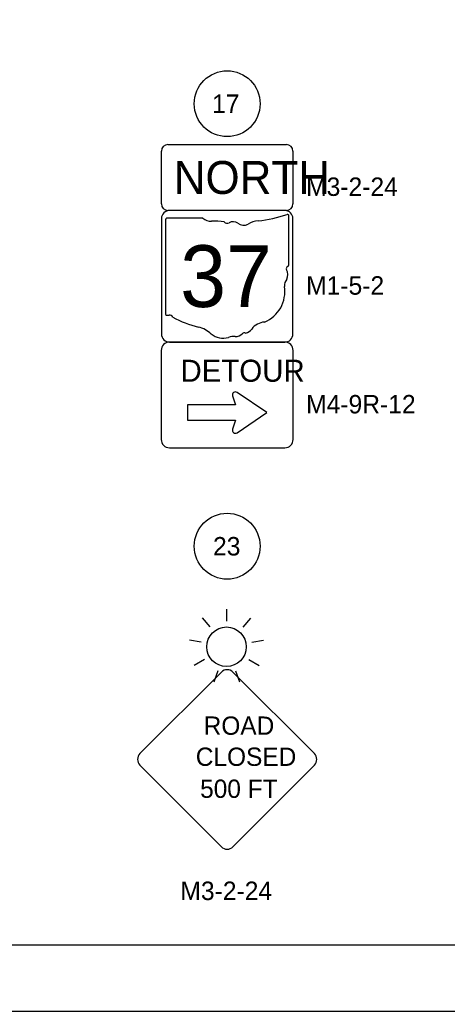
# Model space of a CAD drawing. Extents: x 0 to 680, y 0 to 440.
# Drawn here: x 514.2 to 579.2, y 0 to 150.5 of the extents above; entities that cross this region are included whole.
import ezdxf

# ---------------------------------------------------------------- set-up
doc = ezdxf.new("R2010")
doc.units = 0
for name, color, linetype in [('AP_X_Lights', 7, 'Continuous'), ('SH_Border', 7, 'Continuous'), ('SH_Cut_Line', 7, 'Continuous'), ('SN_P_Signs', 7, 'Continuous'), ('SN_P_Text', 7, 'Continuous')]:
    doc.layers.add(name, color=color, linetype=linetype)

msp = doc.modelspace()

# ---------------------------------------------------------------- linework, layer by layer
at = {"layer": 'AP_X_Lights'}
for p, q in [((545.7, 59.24), (545.7, 61.04)), ((543.18, 58.35), (542.02, 59.73)), ((548.19, 58.31), (549.34, 59.69)), ((541.82, 56.03), (540.05, 56.34)), ((549.5, 56.02), (551.27, 56.33)), ((542.29, 53.38), (540.73, 52.48)), ((549.05, 53.41), (550.61, 52.51)), ((544.36, 51.66), (543.74, 49.97)), ((547.03, 51.69), (547.65, 50))]:
    msp.add_line(p, q, dxfattribs=at)
msp.add_circle((545.66, 55.34), 3, dxfattribs=at)
at = {"layer": 'SH_Border'}
msp.add_lwpolyline([(30, 430), (670, 430), (670, 10), (30, 10)], close=True, dxfattribs=at)
at = {"layer": 'SH_Cut_Line'}
msp.add_lwpolyline([(0, 0), (680, 0), (680, 440), (0, 440)], close=True, dxfattribs=at)
at = {"layer": 'SN_P_Signs'}
for p, q in [((536.76, 131.6), (554.76, 131.6)), ((535.76, 122.6), (535.76, 130.6)), ((555.76, 130.6), (555.76, 122.6)), ((554.76, 121.6), (536.76, 121.6)), ((555.12, 113.31), (555.12, 120.76)), ((536.37, 120.16), (536.37, 105.93)), ((542.05, 120.4), (536.56, 120.4)), ((555.12, 113.31), (555.12, 113.31)), ((546.58, 93.44), (547.01, 92.07)), ((551.78, 90.9), (547.27, 93.96)), ((547.01, 92.07), (539.74, 92.07)), ((539.74, 92.07), (539.74, 89.73)), ((547.27, 87.84), (551.78, 90.9)), ((539.74, 89.73), (547.01, 89.73)), ((547.01, 89.73), (546.58, 88.36))]:
    msp.add_line(p, q, dxfattribs=at)
for points in [[(554.51, 121.6), (537.01, 121.6)], [(535.76, 120.35), (535.76, 102.85)], [(555.76, 102.85), (555.76, 120.35)], [(537.01, 101.6), (554.51, 101.6)], [(554.51, 101.6), (537.01, 101.6)], [(535.73, 100.32), (535.73, 86.83)], [(555.79, 86.83), (555.79, 100.32)], [(537.01, 85.54), (554.51, 85.54)], [(532.5, 39.11), (544.88, 51.48)], [(546.64, 51.48), (559.02, 39.11)], [(544.88, 24.97), (532.5, 37.34)], [(559.02, 37.34), (546.64, 24.97)]]:
    msp.add_lwpolyline(points, dxfattribs=at)
for centre in [(545.76, 137.8), (545.76, 70.6)]:
    msp.add_circle(centre, 5, dxfattribs=at)
for centre, radius, start, end in [((536.76, 130.6), 1, 90, 180), ((554.76, 130.6), 1, 0, 90), ((536.76, 122.6), 1, 180, 270), ((554.76, 122.6), 1, 270, 0), ((537.01, 120.35), 1.25, 90, 180), ((548.44, 139.8), 19.88, 275.8445, 288.9065), ((554.51, 120.35), 1.25, 0, 90), ((554.91, 120.79), 0.209, 351.8621, 97.738), ((536.59, 120.19), 0.217, 98.1301, 188.1301), ((543.35, 122.06), 2.11, 231.6195, 271.1119), ((544.05, 112.41), 7.56, 80.4867, 94.9883), ((545.77, 120.26), 0.608, 219.7921, 297.1024), ((546.66, 118.62), 1.26, 54.4667, 119.1411), ((548.29, 120.87), 1.52, 233.8562, 294.8282), ((550.98, 116.06), 4, 97.3462, 120.7689), ((555.07, 112.77), 0.323, 107.944, 210.337), ((554.9, 113.28), 0.223, 289.6038, 7.7341), ((553.02, 111.82), 1.94, 340.033, 23.6496), ((549.56, 109.25), 4.97, 292.3089, 8.9858), ((555.87, 110.2), 1.41, 136.8065, 186.9296), ((536.59, 105.9), 0.219, 171.9584, 258.3066), ((536.62, 107.35), 1.67, 267.339, 280.6039), ((536.96, 105.11), 0.603, 29.7484, 93.2717), ((544.58, 117.89), 14.36, 240.4129, 257.1985), ((540.3, 99.53), 4.49, 47.1842, 75.836), ((551.65, 101.93), 2.72, 94.4031, 142.5768), ((537.01, 102.85), 1.25, 180, 270), ((545.15, 105.04), 2.85, 230.7004, 286.2918), ((546.8, 100.12), 2.34, 85.6951, 111.2099), ((547.01, 103.97), 1.52, 268.777, 315.5493), ((548.38, 102.59), 0.428, 65.7517, 132.6484), ((548.2, 104.55), 1.61, 282.8732, 323.2771), ((554.51, 102.85), 1.25, 270, 0), ((537.01, 100.32), 1.28, 90, 180), ((554.51, 100.32), 1.28, 0, 90), ((547.01, 93.58), 0.459, 55.8031, 197.8008), ((547.01, 88.22), 0.459, 162.1992, 304.1969), ((537.01, 86.83), 1.28, 180, 270), ((554.51, 86.83), 1.28, 270, 0), ((545.76, 50.6), 1.25, 45, 135), ((533.39, 38.23), 1.25, 135, 225), ((558.13, 38.23), 1.25, 315, 45), ((545.76, 25.85), 1.25, 225, 315)]:
    msp.add_arc(centre, radius, start, end, dxfattribs=at)

# ---------------------------------------------------------------- texts
for s, height, p in [('17', 2.8, (543.46, 136.4)), ('NORTH', 5, (537.63, 124.1)), ('37', 9.375, (538.62, 106.93)), ('DETOUR', 3.345, (538.66, 95.58)), ('23', 2.8, (543.61, 69.2)), ('ROAD', 2.778, (542.19, 41.97)), ('CLOSED', 2.778, (540.99, 37.25)), ('500 FT', 2.778, (541.65, 32.39))]:
    msp.add_text(s, height=height, dxfattribs=at).set_placement(p)
at = {"layer": 'SN_P_Text'}
for s, p in [('M3-2-24', (557.76, 123.8)), ('M1-5-2', (557.76, 108.8)), ('M4-9R-12', (557.76, 90.77)), ('M3-2-24', (538.65, 16.88))]:
    msp.add_text(s, height=2.8, dxfattribs=at).set_placement(p)

doc.saveas('drawing.dxf')
